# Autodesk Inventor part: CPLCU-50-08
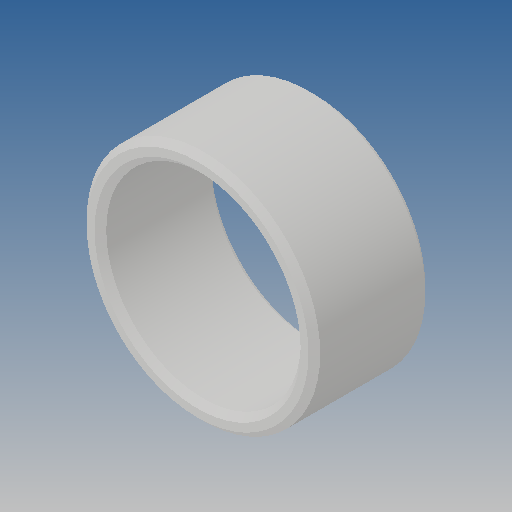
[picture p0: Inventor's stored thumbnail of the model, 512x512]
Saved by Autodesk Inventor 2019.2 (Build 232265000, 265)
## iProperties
Created: 2010-03
Part Number: CPLCU-50-08
Material: Ogólny
Document SubType Name: Modeling
Designer: CADENGINEERING4
Density: 1 g/cm^3
Appearance: Domyślna
Author: CADENGINEERING4
Revision Number: 2LAST_VERSION
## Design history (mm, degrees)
feature "Baza1"
node "Bryła1"
